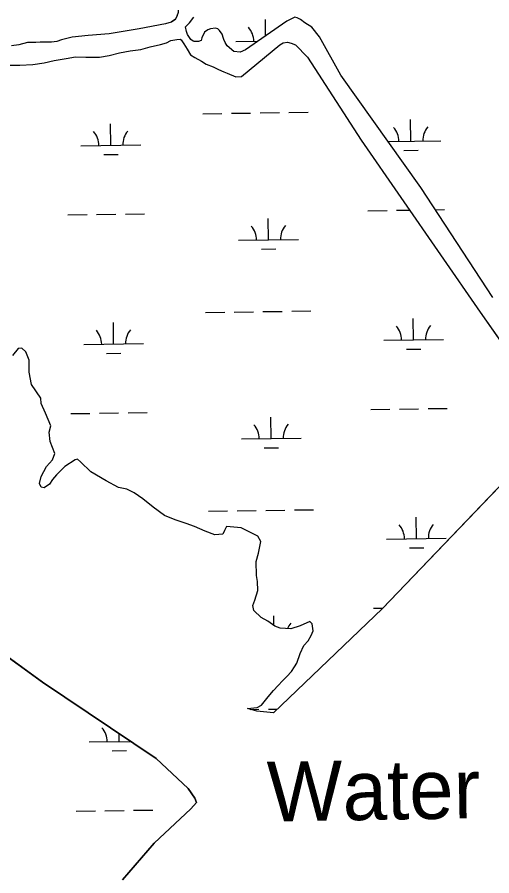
# Model space of a CAD drawing. Extents: x 3767014 to 3805179, y 361544 to 387384.
# Drawn here: x 3774339 to 3775133, y 380479 to 381917 of the extents above; entities that cross this region are included whole.
import ezdxf

# ---------------------------------------------------------------- set-up
doc = ezdxf.new("R2010")
doc.units = 0
for name, color, linetype in [('V-RIVR-IDEN', 7, 'Continuous'), ('V-TOPO-SHOR', 7, 'Continuous'), ('V-WETL-SWMP', 7, 'Continuous')]:
    doc.layers.add(name, color=color, linetype=linetype)

msp = doc.modelspace()

# ---------------------------------------------------------------- linework, layer by layer
at = {"layer": 'V-TOPO-SHOR'}
for points in [[(3774638.835, 380602.297), (3774635.73, 380609.26), (3774624.874, 380625.501), (3774571.401, 380675.753), (3774380.824, 380803.245), (3774203.406, 380932.3), (3774087.962, 381018.856), (3773888.083, 381157.946), (3773733.126, 381275.419), (3773493.739, 381438.459), (3773394.571, 381509.553), (3773149.738, 381695.034), (3773000.992, 381797.807), (3772777.086, 381961.639), (3772530.71, 382143.247), (3772374.167, 382252.778)], [(3774596.245, 381908.043), (3774596.782, 381908.579), (3774603.229, 381913.429), (3774604.304, 381914.506), (3774606.45, 381918.811), (3774608.594, 381924.73), (3774608.588, 381928.494), (3774604.277, 381936.557), (3774599.968, 381941.392), (3774589.732, 381955.362), (3774535.329, 382024.138), (3774505.164, 382063.363), (3774498.697, 382074.649), (3774495.999, 382080.562), (3774495.999, 382081.637), (3774495.987, 382090.779), (3774497.597, 382095.084), (3774505.652, 382104.237), (3774526.068, 382120.934), (3774576.044, 382157.028), (3774586.091, 382164.78)], [(3774596.245, 381908.043), (3774586.566, 381905.341), (3774542.475, 381897.221), (3774492.469, 381888.554), (3774457.513, 381885.824), (3774430.625, 381883.1), (3774412.881, 381878.777), (3774404.818, 381876.077), (3774396.215, 381874.453), (3774386.534, 381874.443), (3774376.853, 381874.431), (3774369.861, 381873.884), (3774355.879, 381873.868), (3774341.361, 381870.085), (3774328.993, 381868.457)], [(3774620.454, 381900.543), (3774626.901, 381907.004), (3774633.881, 381916.693)], [(3775134.087, 381447.243), (3775013.928, 381631.569), (3774880.321, 381819.645), (3774844.211, 381883.602), (3774831.284, 381899.722), (3774819.979, 381907.238), (3774812.442, 381912.606), (3774807.062, 381915.288), (3774803.296, 381916.36), (3774789.859, 381909.89), (3774720.536, 381861.94), (3774711.4, 381858.164), (3774701.178, 381859.226), (3774689.873, 381868.356), (3774686.64, 381874.269), (3774684.481, 381879.106), (3774683.942, 381880.718), (3774681.782, 381888.247), (3774676.934, 381894.155), (3774674.241, 381896.842), (3774670.477, 381897.913), (3774661.871, 381896.828), (3774657.572, 381895.208), (3774652.198, 381891.437), (3774647.369, 381881.75), (3774646.298, 381877.445), (3774641.997, 381875.828)], [(3774641.997, 381875.828), (3774634.469, 381875.819), (3774632.855, 381876.356), (3774629.087, 381879.039), (3774628.009, 381880.651), (3774623.698, 381887.638), (3774622.078, 381892.476), (3774620.454, 381900.543)], [(3774325.27, 381836.182), (3774343.018, 381836.205), (3774365.067, 381837.307), (3774383.888, 381840.018), (3774400.554, 381843.805), (3774420.451, 381847.594), (3774436.042, 381850.301), (3774453.254, 381849.783), (3774476.38, 381849.812), (3774492.512, 381852.519), (3774509.717, 381856.845), (3774527.461, 381860.093), (3774545.207, 381862.266), (3774561.335, 381867.126), (3774578.54, 381870.91), (3774588.219, 381873.612), (3774595.743, 381877.384), (3774605.961, 381879.01), (3774611.339, 381879.555), (3774612.953, 381878.482), (3774617.264, 381872.033), (3774623.191, 381862.896), (3774628.579, 381853.76), (3774635.577, 381848.929), (3774646.878, 381843.027), (3774654.953, 381837.659), (3774666.252, 381833.368), (3774675.4, 381829.078), (3774684.549, 381824.785), (3774689.929, 381822.641), (3774704.457, 381816.743), (3774714.136, 381817.294), (3774778.075, 381870.077), (3774783.449, 381873.311), (3774790.977, 381874.933), (3774796.896, 381872.788), (3774804.428, 381870.11), (3774824.351, 381849.695), (3774914.336, 381710.509), (3775113.142, 381423.015), (3775183.179, 381322.528)], [(3774767.265, 380752.356), (3774949.869, 380926.836), (3775170.912, 381157.76), (3775458.377, 381461.503), (3775635.521, 381647.254)], [(3774723.909, 380759.27), (3774740.162, 380760.839), (3774747.125, 380764.718), (3774758.719, 380778.665), (3774767.22, 380789.511), (3774774.951, 380798.037), (3774782.683, 380805.786), (3774789.642, 380812.762), (3774797.371, 380821.286), (3774802.78, 380829.033), (3774806.642, 380835.231), (3774812.043, 380851.494), (3774818.217, 380864.658), (3774825.177, 380872.41), (3774830.583, 380881.704), (3774833.67, 380889.449), (3774832.107, 380901.057), (3774828.232, 380904.924), (3774811.985, 380897.936), (3774796.511, 380892.501), (3774778.705, 380894.027), (3774769.412, 380897.111), (3774757.791, 380905.612), (3774746.945, 380911.793), (3774734.546, 380923.389), (3774732.99, 380931.9), (3774736.074, 380940.42), (3774741.473, 380956.681), (3774740.68, 380972.162), (3774739.12, 380982.224), (3774738.319, 381005.444), (3774742.171, 381019.383), (3774746.017, 381038.738), (3774741.362, 381048.022), (3774713.479, 381061.922), (3774688.706, 381064.213), (3774685.618, 381057.244), (3774682.529, 381051.047), (3774669.371, 381050.256), (3774653.108, 381056.431), (3774635.294, 381064.15), (3774621.356, 381068.776), (3774602.772, 381074.947), (3774584.958, 381082.666), (3774566.363, 381096.578), (3774548.543, 381110.488), (3774534.596, 381120.535), (3774522.204, 381126.712), (3774508.267, 381129.016), (3774487.355, 381140.604), (3774461.792, 381155.28), (3774444.742, 381172.288), (3774439.317, 381176.927), (3774435.448, 381175.375), (3774418.431, 381164.516), (3774404.515, 381150.565), (3774397.558, 381142.818), (3774392.924, 381135.07), (3774383.642, 381128.867), (3774378.997, 381129.635), (3774375.892, 381135.824), (3774378.975, 381147.44), (3774387.47, 381164.479), (3774397.519, 381175.328), (3774401.378, 381186.17), (3774393.612, 381206.285), (3774392.043, 381221.766), (3774395.127, 381232.606), (3774385.813, 381253.496), (3774378.827, 381269.742), (3774378.043, 381279.03), (3774362.533, 381301.46), (3774358.636, 381322.356), (3774358.613, 381342.481), (3774353.178, 381356.408), (3774346.203, 381362.593), (3774340.012, 381361.81), (3774330.736, 381350.188)], [(3774767.265, 380752.356), (3774739.396, 380754.646), (3774723.909, 380759.27)], [(3774514.778, 380472.773), (3774567.602, 380533.904), (3774629.378, 380591.158), (3774638.835, 380602.297)]]:
    msp.add_lwpolyline(points, dxfattribs=at)
at = {"layer": 'V-WETL-SWMP'}
for p, q in [((3774620.455, 381900.542), (3774626.901, 381907.004)), ((3774626.901, 381907.004), (3774633.881, 381916.693)), ((3774789.858, 381909.89), (3774720.537, 381861.94)), ((3774754.264, 381885.269), (3774753.887, 381912.452)), ((3774803.296, 381916.36), (3774789.858, 381909.89)), ((3774807.062, 381915.289), (3774803.296, 381916.36)), ((3774812.443, 381912.606), (3774807.062, 381915.289)), ((3774819.979, 381907.237), (3774812.443, 381912.606)), ((3774831.283, 381899.721), (3774819.979, 381907.237)), ((3774622.079, 381892.476), (3774620.455, 381900.542)), ((3774623.698, 381887.638), (3774622.079, 381892.476)), ((3774652.198, 381891.437), (3774647.369, 381881.75)), ((3774657.572, 381895.208), (3774652.198, 381891.437)), ((3774661.872, 381896.827), (3774657.572, 381895.208)), ((3774670.476, 381897.913), (3774661.872, 381896.827)), ((3774674.242, 381896.842), (3774670.476, 381897.913)), ((3774676.934, 381894.156), (3774674.242, 381896.842)), ((3774681.782, 381888.246), (3774676.934, 381894.156)), ((3774844.21, 381883.602), (3774831.283, 381899.721)), ((3774588.219, 381873.611), (3774595.744, 381877.385)), ((3774595.744, 381877.385), (3774605.96, 381879.011)), ((3774605.96, 381879.011), (3774611.338, 381879.555)), ((3774611.338, 381879.555), (3774612.953, 381878.482)), ((3774612.953, 381878.482), (3774617.263, 381872.033)), ((3774628.009, 381880.651), (3774623.698, 381887.638)), ((3774629.087, 381879.039), (3774628.009, 381880.651)), ((3774632.855, 381876.355), (3774629.087, 381879.039)), ((3774634.469, 381875.819), (3774632.855, 381876.355)), ((3774641.998, 381875.828), (3774634.469, 381875.819)), ((3774646.299, 381877.446), (3774641.998, 381875.828)), ((3774647.369, 381881.75), (3774646.299, 381877.446)), ((3774683.942, 381880.719), (3774681.782, 381888.246)), ((3774684.482, 381879.106), (3774683.942, 381880.719)), ((3774686.639, 381874.268), (3774684.482, 381879.106)), ((3774704.391, 381875.761), (3774741.258, 381876.273)), ((3774880.322, 381819.645), (3774844.21, 381883.602)), ((3774527.461, 381860.092), (3774545.207, 381862.265)), ((3774545.207, 381862.265), (3774561.335, 381867.125)), ((3774561.335, 381867.125), (3774578.541, 381870.91)), ((3774578.541, 381870.91), (3774588.219, 381873.611)), ((3774617.263, 381872.033), (3774623.19, 381862.897)), ((3774623.19, 381862.897), (3774628.579, 381853.761)), ((3774689.873, 381868.356), (3774686.639, 381874.268)), ((3774701.179, 381859.227), (3774689.873, 381868.356)), ((3774720.537, 381861.94), (3774711.399, 381858.164)), ((3774714.137, 381817.293), (3774778.074, 381870.077)), ((3774778.074, 381870.077), (3774783.449, 381873.31)), ((3774783.449, 381873.31), (3774790.976, 381874.933)), ((3774790.976, 381874.933), (3774796.895, 381872.789)), ((3774796.895, 381872.789), (3774804.428, 381870.109)), ((3774804.428, 381870.109), (3774824.352, 381849.695)), ((3774400.555, 381843.804), (3774420.45, 381847.593)), ((3774420.45, 381847.593), (3774436.043, 381850.301)), ((3774436.043, 381850.301), (3774453.254, 381849.784)), ((3774453.254, 381849.784), (3774476.38, 381849.812)), ((3774476.38, 381849.812), (3774492.512, 381852.52)), ((3774492.512, 381852.52), (3774509.717, 381856.844)), ((3774509.717, 381856.844), (3774527.461, 381860.092)), ((3774628.579, 381853.761), (3774635.577, 381848.929)), ((3774635.577, 381848.929), (3774646.878, 381843.027)), ((3774711.399, 381858.164), (3774701.179, 381859.227)), ((3774824.352, 381849.695), (3774914.337, 381710.509)), ((3774325.269, 381836.183), (3774343.017, 381836.204)), ((3774343.017, 381836.204), (3774365.066, 381837.307)), ((3774365.066, 381837.307), (3774383.887, 381840.019)), ((3774383.887, 381840.019), (3774400.555, 381843.804)), ((3774646.878, 381843.027), (3774654.952, 381837.658)), ((3774654.952, 381837.658), (3774666.252, 381833.369)), ((3774666.252, 381833.369), (3774675.4, 381829.078)), ((3774675.4, 381829.078), (3774684.548, 381824.786)), ((3774684.548, 381824.786), (3774689.929, 381822.641)), ((3774689.929, 381822.641), (3774704.457, 381816.743)), ((3775013.929, 381631.569), (3774880.322, 381819.645)), ((3774704.457, 381816.743), (3774714.137, 381817.293)), ((3774649.221, 381754.912), (3774681.218, 381755.356)), ((3774697.216, 381755.578), (3774729.213, 381756.023)), ((3774745.211, 381756.245), (3774777.208, 381756.69)), ((3774793.207, 381756.912), (3774825.204, 381757.356)), ((3774495.348, 381702.027), (3774494.848, 381738.024)), ((3774997.208, 381708.999), (3774996.708, 381744.995)), ((3774914.337, 381710.509), (3775113.142, 381423.014)), ((3774959.298, 381708.472), (3775047.203, 381709.693)), ((3774445.353, 381701.333), (3774545.344, 381702.722)), ((3774985.423, 381693.403), (3775009.421, 381693.736)), ((3774483.564, 381686.431), (3774507.562, 381686.765)), ((3775134.087, 381447.242), (3775013.929, 381631.569)), ((3774925.41, 381592.558), (3774957.407, 381593.003)), ((3774973.406, 381593.225), (3774995.23, 381593.528)), ((3775038.336, 381594.127), (3775053.398, 381594.336)), ((3774423.551, 381585.587), (3774455.548, 381586.031)), ((3774471.546, 381586.254), (3774503.543, 381586.698)), ((3774519.542, 381586.92), (3774551.538, 381587.365)), ((3774759.007, 381543.812), (3774758.507, 381579.809)), ((3774709.012, 381543.118), (3774809.003, 381544.507)), ((3774747.223, 381528.216), (3774771.221, 381528.549)), ((3774653.841, 381422.269), (3774685.838, 381422.713)), ((3774701.837, 381422.936), (3774733.834, 381423.38)), ((3774749.832, 381423.602), (3774781.829, 381424.047)), ((3774797.828, 381424.269), (3774829.825, 381424.713)), ((3775113.142, 381423.014), (3775183.18, 381322.527)), ((3774499.969, 381369.384), (3774499.469, 381405.381)), ((3775001.829, 381376.356), (3775001.329, 381412.352)), ((3774951.834, 381375.661), (3775051.824, 381377.05)), ((3774340.012, 381361.81), (3774330.737, 381350.188)), ((3774346.203, 381362.592), (3774340.012, 381361.81)), ((3774353.178, 381356.408), (3774346.203, 381362.592)), ((3774449.974, 381368.69), (3774549.964, 381370.079)), ((3774990.044, 381360.76), (3775014.042, 381361.093)), ((3774358.613, 381342.481), (3774353.178, 381356.408)), ((3774488.185, 381353.788), (3774512.182, 381354.122)), ((3774358.637, 381322.355), (3774358.613, 381342.481)), ((3774362.533, 381301.46), (3774358.637, 381322.355)), ((3774378.042, 381279.03), (3774362.533, 381301.46)), ((3774378.827, 381269.742), (3774378.042, 381279.03)), ((3774385.813, 381253.495), (3774378.827, 381269.742)), ((3774930.031, 381259.915), (3774962.028, 381260.36)), ((3774978.027, 381260.582), (3775010.023, 381261.027)), ((3775026.022, 381261.249), (3775058.019, 381261.693)), ((3774395.128, 381232.606), (3774385.813, 381253.495)), ((3774428.172, 381252.944), (3774460.169, 381253.388)), ((3774476.167, 381253.611), (3774508.164, 381254.055)), ((3774524.162, 381254.277), (3774556.159, 381254.722)), ((3774763.628, 381211.169), (3774763.128, 381247.166)), ((3774392.044, 381221.766), (3774395.128, 381232.606)), ((3774393.611, 381206.286), (3774392.044, 381221.766)), ((3774401.377, 381186.169), (3774393.611, 381206.286)), ((3774713.633, 381210.475), (3774813.623, 381211.864)), ((3774397.519, 381175.328), (3774401.377, 381186.169)), ((3774751.844, 381195.573), (3774775.841, 381195.907)), ((3774387.469, 381164.479), (3774397.519, 381175.328)), ((3774435.449, 381175.374), (3774418.432, 381164.516)), ((3774439.317, 381176.927), (3774435.449, 381175.374)), ((3774444.742, 381172.289), (3774439.317, 381176.927)), ((3774461.792, 381155.28), (3774444.742, 381172.289)), ((3774378.975, 381147.439), (3774387.469, 381164.479)), ((3774418.432, 381164.516), (3774404.516, 381150.566)), ((3775170.911, 381157.76), (3774949.869, 380926.835)), ((3774375.893, 381135.824), (3774378.975, 381147.439)), ((3774397.559, 381142.817), (3774392.924, 381135.07)), ((3774404.516, 381150.566), (3774397.559, 381142.817)), ((3774487.354, 381140.603), (3774461.792, 381155.28)), ((3774378.997, 381129.635), (3774375.893, 381135.824)), ((3774383.642, 381128.866), (3774378.997, 381129.635)), ((3774392.924, 381135.07), (3774383.642, 381128.866)), ((3774508.268, 381129.017), (3774487.354, 381140.603)), ((3774522.204, 381126.712), (3774508.268, 381129.017)), ((3774534.597, 381120.535), (3774522.204, 381126.712)), ((3774548.542, 381110.488), (3774534.597, 381120.535)), ((3774566.363, 381096.577), (3774548.542, 381110.488)), ((3774584.958, 381082.666), (3774566.363, 381096.577)), ((3774658.462, 381089.626), (3774690.459, 381090.07)), ((3774706.458, 381090.293), (3774738.455, 381090.737)), ((3774754.453, 381090.959), (3774786.45, 381091.404)), ((3774802.448, 381091.626), (3774834.445, 381092.071)), ((3774602.771, 381074.947), (3774584.958, 381082.666)), ((3774621.356, 381068.777), (3774602.771, 381074.947)), ((3775006.45, 381043.713), (3775005.95, 381079.709)), ((3774635.295, 381064.149), (3774621.356, 381068.777)), ((3774653.108, 381056.43), (3774635.295, 381064.149)), ((3774669.371, 381050.257), (3774653.108, 381056.43)), ((3774685.618, 381057.243), (3774682.529, 381051.047)), ((3774688.706, 381064.214), (3774685.618, 381057.243)), ((3774713.479, 381061.922), (3774688.706, 381064.214)), ((3774741.363, 381048.022), (3774713.479, 381061.922)), ((3774682.529, 381051.047), (3774669.371, 381050.257)), ((3774746.018, 381038.739), (3774741.363, 381048.022)), ((3774956.454, 381043.018), (3775056.445, 381044.407)), ((3774742.172, 381019.382), (3774746.018, 381038.739)), ((3774994.665, 381028.117), (3775018.663, 381028.45)), ((3774738.318, 381005.444), (3774742.172, 381019.382)), ((3774739.12, 380982.223), (3774738.318, 381005.444)), ((3774740.681, 380972.162), (3774739.12, 380982.223)), ((3774741.473, 380956.681), (3774740.681, 380972.162)), ((3774736.075, 380940.419), (3774741.473, 380956.681)), ((3774203.405, 380932.299), (3774380.825, 380803.244)), ((3774732.989, 380931.901), (3774736.075, 380940.419)), ((3774734.547, 380923.388), (3774732.989, 380931.901)), ((3774949.869, 380926.835), (3774767.266, 380752.357)), ((3774934.652, 380927.272), (3774950.498, 380927.493)), ((3774746.946, 380911.792), (3774734.547, 380923.388)), ((3774767.976, 380898.161), (3774767.749, 380914.523)), ((3774757.791, 380905.612), (3774746.946, 380911.792)), ((3774769.412, 380897.111), (3774757.791, 380905.612)), ((3774828.233, 380904.923), (3774811.985, 380897.937)), ((3774832.108, 380901.058), (3774828.233, 380904.923)), ((3774833.67, 380889.449), (3774832.108, 380901.058)), ((3774778.705, 380894.026), (3774769.412, 380897.111)), ((3774796.511, 380892.5), (3774778.705, 380894.026)), ((3774811.985, 380897.937), (3774796.511, 380892.5)), ((3774830.583, 380881.704), (3774833.67, 380889.449)), ((3774818.218, 380864.659), (3774825.176, 380872.409)), ((3774825.176, 380872.409), (3774830.583, 380881.704)), ((3774812.042, 380851.493), (3774818.218, 380864.659)), ((3774806.643, 380835.231), (3774812.042, 380851.493)), ((3774797.371, 380821.286), (3774802.78, 380829.033)), ((3774802.78, 380829.033), (3774806.643, 380835.231)), ((3774782.682, 380805.787), (3774789.641, 380812.762)), ((3774789.641, 380812.762), (3774797.371, 380821.286)), ((3774380.825, 380803.244), (3774571.401, 380675.752)), ((3774767.221, 380789.512), (3774774.951, 380798.037)), ((3774774.951, 380798.037), (3774782.682, 380805.787)), ((3774758.719, 380778.665), (3774767.221, 380789.512)), ((3774747.125, 380764.718), (3774758.719, 380778.665)), ((3774723.909, 380759.271), (3774740.163, 380760.839)), ((3774739.397, 380754.645), (3774723.909, 380759.271)), ((3774728.525, 380757.892), (3774743.075, 380758.094)), ((3774767.266, 380752.357), (3774739.397, 380754.645)), ((3774740.163, 380760.839), (3774747.125, 380764.718)), ((3774759.074, 380758.316), (3774773.716, 380758.52)), ((3774509.211, 380704.099), (3774509.025, 380717.481)), ((3774459.215, 380703.404), (3774528.625, 380704.368)), ((3774497.426, 380688.502), (3774521.424, 380688.836)), ((3774571.401, 380675.752), (3774624.874, 380625.502)), ((3774624.874, 380625.502), (3774635.73, 380609.26)), ((3774638.835, 380602.297), (3774629.378, 380591.158)), ((3774635.73, 380609.26), (3774638.835, 380602.297)), ((3774437.413, 380587.658), (3774469.41, 380588.103)), ((3774485.408, 380588.325), (3774517.405, 380588.769)), ((3774533.404, 380588.992), (3774565.401, 380589.436)), ((3774629.378, 380591.158), (3774567.602, 380533.905)), ((3774567.602, 380533.905), (3774514.777, 380472.773))]:
    msp.add_line(p, q, dxfattribs=at)
msp.add_lwpolyline([(3774606.45, 381918.811), (3774604.304, 381914.506), (3774603.229, 381913.429), (3774596.781, 381908.58), (3774596.244, 381908.042), (3774586.567, 381905.341), (3774542.475, 381897.22), (3774492.468, 381888.554), (3774457.513, 381885.823), (3774430.625, 381883.101), (3774412.882, 381878.777), (3774404.818, 381876.078), (3774396.215, 381874.454), (3774386.534, 381874.443), (3774376.853, 381874.431), (3774369.862, 381873.885), (3774355.879, 381873.868), (3774341.362, 381870.085), (3774328.994, 381868.457)], dxfattribs=at)
for centre, start, end in [((3774699.142, 381876.163), 0.024037, 41.567696), ((3774941.964, 381708.706), 0.024037, 41.567696), ((3775052.439, 381710.241), 140.024034, 181.567693), ((3774440.104, 381701.735), 0.024037, 41.567696), ((3774550.579, 381703.269), 140.024034, 181.567693), ((3774703.763, 381543.52), 0.024037, 41.567696), ((3774814.238, 381545.054), 140.024034, 181.567693), ((3774444.725, 381369.092), 0.024037, 41.567696), ((3774555.2, 381370.627), 140.024034, 181.567693), ((3774946.585, 381376.063), 0.024037, 41.567696), ((3775057.06, 381377.598), 140.024034, 181.567693), ((3774708.384, 381210.877), 0.024037, 41.567696), ((3774818.859, 381212.411), 140.024034, 181.567693), ((3774951.205, 381043.42), 0.024037, 41.567696), ((3775061.681, 381044.955), 140.024034, 181.567693), ((3774823.48, 380879.769), 140.024034, 157.970641), ((3774453.966, 380703.806), 0.024037, 41.567696)]:
    msp.add_arc(centre, 35.246, start, end, dxfattribs=at)

# ---------------------------------------------------------------- texts
at = {"layer": 'V-RIVR-IDEN'}
msp.add_text('Water', height=100, rotation=0.919589, dxfattribs=at).set_placement((3774757.352, 380570.102))

doc.saveas('drawing.dxf')
